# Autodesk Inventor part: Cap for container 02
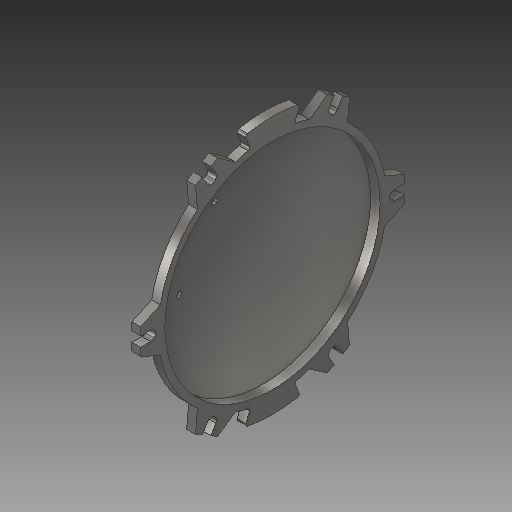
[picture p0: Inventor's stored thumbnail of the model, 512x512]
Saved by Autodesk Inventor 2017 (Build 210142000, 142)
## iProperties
Created: 2020-03
Part Number: Cap for container 02
Material: Stainless Steel
Document SubType Name: Modeling
Designer: user
Density: 8 g/cm^3
Appearance: Semi-Polished
Mass: 1002.46 g
Surface Area: 915.657 cm^2
Volume: 125.308 cm^3
Author: user
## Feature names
1. Revolution1
2. Extrusion1
3. Fillet1
4. Fillet2
5. Extrusion2
6. Circular Pattern1
7. Extrusion3
8. Fillet3
9. Sweep1
10. Circular Pattern2
## Parameters: d3 = 2 mm, d4 = 2 mm, d5 = 90 deg, d6 = 208 mm, d7 = 8 mm, d8 = 0, d9 = 2 mm, d10 = 2 mm, d14 = 50 deg, d15 = 9 mm, d16 = 9 mm, d17 = 8 mm, d18 = 0, d20 = 360 deg, d22 = 235 mm, d25 = 8 mm, d26 = 0, d27 = 2 mm, d28 = 6 mm, d29 = 0, d30 = 0, d32 = 0, d34 = 60 deg
